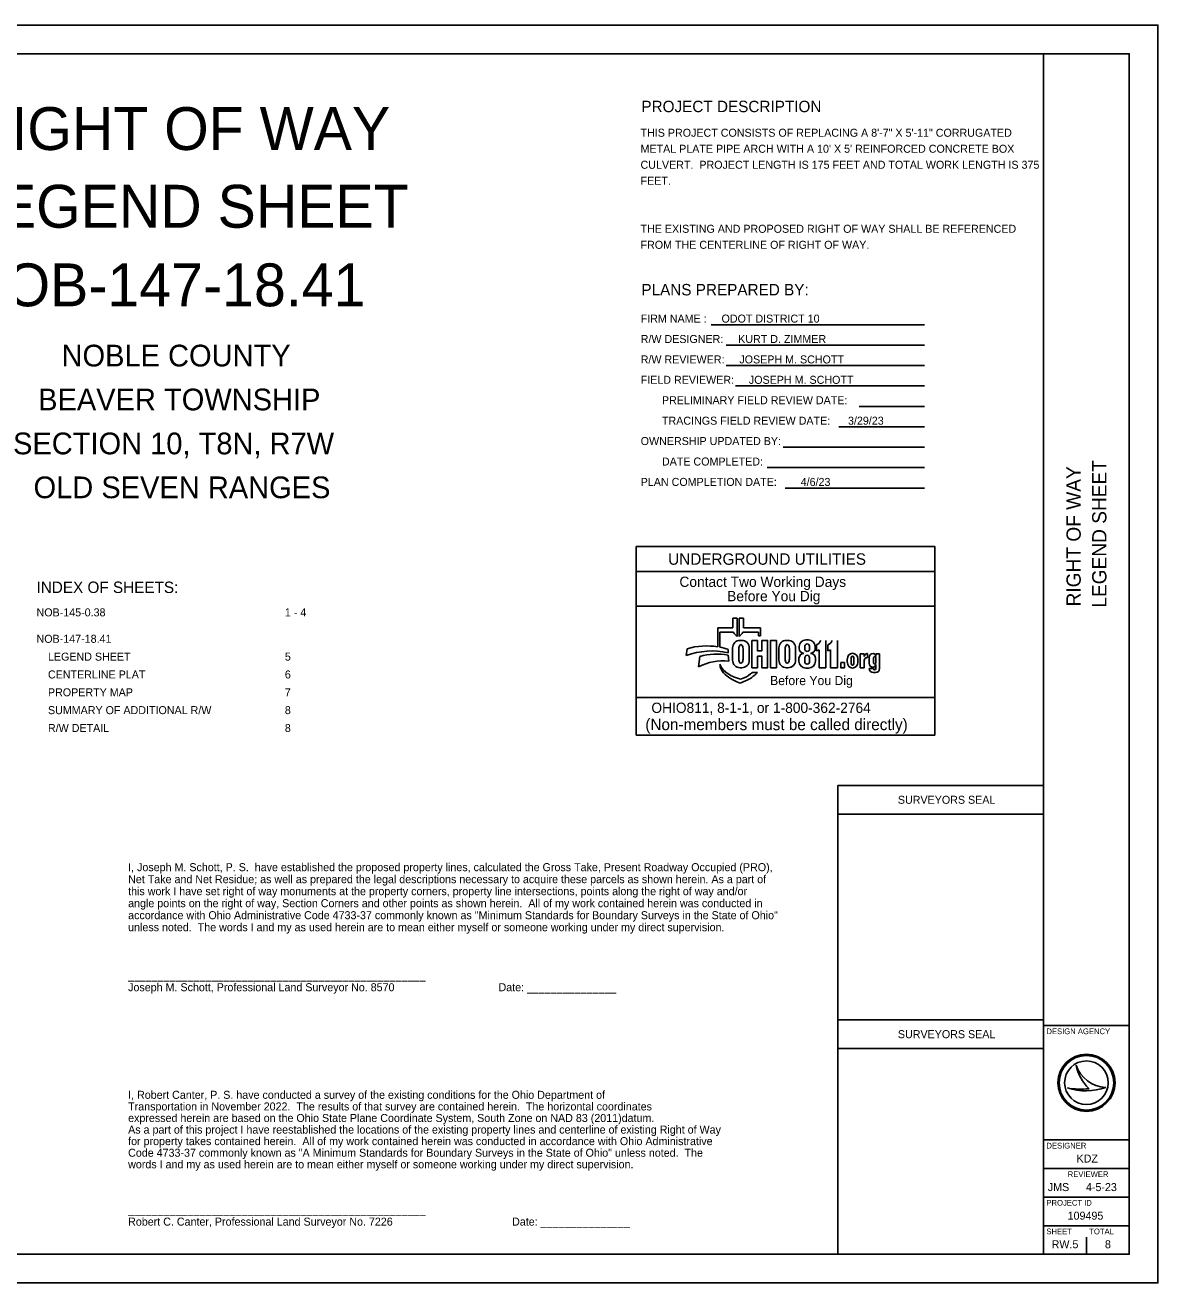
# Model space of a CAD drawing. Extents: x 0 to 34, y 0 to 22.
# Drawn here: x 14.18 to 34, y 0 to 22 of the extents above; entities that cross this region are included whole.
import ezdxf

# ---------------------------------------------------------------- set-up
doc = ezdxf.new("R2010")
doc.units = 0
for name, color, linetype in [('SH_Border', 7, 'Continuous'), ('SH_Cut_Line', 7, 'Continuous'), ('SH_Data', 7, 'Continuous'), ('SH_Text', 7, 'Continuous')]:
    doc.layers.add(name, color=color, linetype=linetype)

msp = doc.modelspace()

# ---------------------------------------------------------------- linework, layer by layer
at = {"layer": 'SH_Border'}
for p, q in [((32, 0.5), (32, 21.5)), ((32, 4.5), (33.5, 4.5)), ((32, 2.5), (33.5, 2.5)), ((32, 2), (33.5, 2)), ((32, 1.5), (33.5, 1.5)), ((32, 1), (33.5, 1))]:
    msp.add_line(p, q, dxfattribs=at)
msp.add_lwpolyline([(1.5, 21.5), (33.5, 21.5), (33.5, 0.5), (1.5, 0.5)], close=True, dxfattribs=at)
at = {"layer": 'SH_Cut_Line'}
msp.add_lwpolyline([(0, 0), (34, 0), (34, 22), (0, 22)], close=True, dxfattribs=at)
at = {"layer": 'SH_Data'}
for p, q in [((26.559, 11.46), (26.296, 11.46)), ((26.296, 11.46), (26.296, 11.125)), ((26.639, 11.626), (26.559, 11.626)), ((26.559, 11.626), (26.559, 11.46)), ((26.639, 11.309), (26.639, 11.626)), ((26.75, 11.626), (26.67, 11.626)), ((26.67, 11.626), (26.67, 11.309)), ((26.75, 11.46), (26.75, 11.626)), ((27.048, 11.46), (26.75, 11.46)), ((27.048, 11.319), (27.048, 11.46)), ((26.334, 11.119), (26.334, 11.383)), ((26.334, 11.383), (26.574, 11.383)), ((26.716, 11.238), (26.691, 11.238)), ((26.735, 11.383), (27.013, 11.383)), ((26.993, 11.237), (26.892, 11.237)), ((26.892, 11.237), (26.892, 10.759)), ((27.013, 11.383), (27.013, 11.319)), ((27.013, 11.319), (27.048, 11.319)), ((27.526, 11.238), (27.502, 11.238)), ((27.887, 11.245), (27.839, 11.245)), ((28.191, 11.237), (28.191, 10.759)), ((28.391, 11.237), (28.391, 10.759)), ((25.761, 11.091), (25.747, 10.974)), ((26.48, 11.023), (26.48, 11.081)), ((26.557, 11.105), (26.557, 10.893)), ((26.666, 10.91), (26.666, 11.092)), ((26.741, 11.092), (26.741, 10.91)), ((26.849, 10.893), (26.849, 11.105)), ((27.368, 11.105), (27.368, 10.893)), ((27.477, 10.91), (27.477, 11.092)), ((27.551, 11.092), (27.551, 10.91)), ((27.66, 10.893), (27.66, 11.105)), ((27.725, 11.131), (27.725, 11.095)), ((27.823, 11.078), (27.823, 11.136)), ((27.904, 11.136), (27.904, 11.078)), ((28.001, 11.095), (28.001, 11.131)), ((28.024, 11.057), (28.024, 11.158)), ((28.073, 10.759), (28.073, 11.071)), ((28.225, 11.057), (28.225, 11.158)), ((28.273, 10.759), (28.273, 11.071)), ((28.86, 11.002), (28.787, 11.002)), ((28.787, 11.002), (28.787, 10.759)), ((28.86, 10.955), (28.86, 11.002)), ((28.921, 11.01), (28.915, 11.01)), ((28.921, 10.936), (28.921, 11.01)), ((29.064, 10.957), (29.064, 11.004)), ((29.064, 11.004), (29.129, 11.004)), ((29.129, 11.004), (29.129, 10.745)), ((25.981, 10.956), (25.959, 10.776)), ((26.333, 10.819), (26.337, 10.792)), ((26.49, 10.873), (26.481, 10.979)), ((26.993, 10.759), (26.993, 10.961)), ((27.719, 10.925), (27.719, 10.874)), ((27.82, 10.865), (27.82, 10.926)), ((27.905, 10.926), (27.905, 10.865)), ((28.007, 10.874), (28.007, 10.925)), ((28.565, 10.85), (28.565, 10.918)), ((28.632, 10.849), (28.632, 10.918)), ((28.68, 10.918), (28.68, 10.849)), ((28.748, 10.918), (28.748, 10.85)), ((28.86, 10.759), (28.86, 10.886)), ((28.909, 10.936), (28.921, 10.936)), ((28.949, 10.837), (28.949, 10.941)), ((29.021, 10.851), (29.021, 10.927)), ((29.064, 10.927), (29.064, 10.851)), ((29.064, 10.745), (29.064, 10.815)), ((26.698, 10.558), (26.609, 10.589)), ((26.691, 10.759), (26.716, 10.759)), ((26.759, 10.585), (26.698, 10.558)), ((26.892, 10.759), (26.993, 10.759)), ((26.991, 10.679), (26.905, 10.679)), ((26.989, 10.676), (26.991, 10.679)), ((27.502, 10.759), (27.526, 10.759)), ((27.84, 10.753), (27.887, 10.753)), ((28.191, 10.759), (28.073, 10.759)), ((28.391, 10.759), (28.273, 10.759)), ((28.787, 10.759), (28.86, 10.759)), ((28.949, 10.745), (29.021, 10.745)), ((29.059, 10.676), (29.019, 10.676)), ((26.633, 10.512), (26.689, 10.488)), ((26.689, 10.488), (26.783, 10.529)), ((30.095, 9.581), (24.87, 9.581)), ((28.4, 8.2), (32, 8.2)), ((28.4, 4.1), (32, 4.1)), ((32.567, 3.81), (32.567, 3.81)), ((32.417, 3.41), (32.417, 3.41)), ((32.75, 3.5), (32.75, 3.5)), ((33.087, 3.419), (33.087, 3.419)), ((32.375, 0.675), (32.375, 0.675)), ((32.75, 0.5), (32.75, 0.8))]:
    msp.add_line(p, q, dxfattribs=at)
for points in [[(24.87, 12.881), (30.095, 12.881), (30.095, 12.441), (24.87, 12.441)], [(24.87, 12.441), (30.095, 12.441), (30.095, 11.836), (24.87, 11.836)], [(24.87, 11.836), (30.095, 11.836), (30.095, 10.241), (24.87, 10.241)], [(28.449, 10.849), (28.515, 10.849), (28.515, 10.759), (28.449, 10.759)], [(24.87, 10.241), (30.095, 10.241), (30.095, 9.581), (24.87, 9.581)], [(28.4, 8.7), (32, 8.7), (32, 4.6), (28.4, 4.6)], [(28.4, 4.6), (32, 4.6), (32, 0.5), (28.4, 0.5)]]:
    msp.add_lwpolyline(points, close=True, dxfattribs=at)
for points in [[(26.993, 10.961), (27.07, 10.961), (27.07, 10.759), (27.171, 10.759), (27.171, 11.237), (27.07, 11.237), (27.07, 11.057), (26.993, 11.057), (26.993, 11.237)], [(27.222, 10.759), (27.325, 10.759), (27.325, 11.237), (27.222, 11.237), (27.222, 10.759)], [(27.805, 11.011), (27.805, 11.011)], [(27.921, 11.011), (27.921, 11.011)]]:
    msp.add_lwpolyline(points, dxfattribs=at)
for radius in [0.5, 0.477, 0.477, 0.382]:
    msp.add_circle((32.75, 3.5), radius, dxfattribs=at)
for centre, radius, start, end in [((26.691, 11.105), 0.134, 90, 180), ((26.711, 11.438), 0.147, 201.9296, 240.7469), ((26.598, 11.438), 0.147, 299.2531, 338.0704), ((26.716, 11.105), 0.134, 0, 90), ((27.502, 11.105), 0.134, 90, 180), ((27.526, 11.105), 0.134, 0, 90), ((27.839, 11.131), 0.114, 90, 180), ((27.887, 11.131), 0.114, 0, 90), ((27.974, 11.281), 0.132, 292.5572, 340.7355), ((28.174, 11.281), 0.132, 292.5572, 340.7355), ((26.199, 9.721), 1.332, 77.8238, 109.8274), ((26.105, 9.917), 1.224, 81.0007, 106.3144), ((26.105, 9.917), 1.224, 72.1402, 79.2074), ((27.805, 10.925), 0.0865, 90, 180), ((27.808, 11.095), 0.0837, 180, 268.1442), ((27.918, 11.095), 0.0837, 272.2058, 0), ((27.921, 10.925), 0.0865, 0, 90), ((28.013, 11.188), 0.132, 275.1733, 297.0931), ((28.213, 11.188), 0.132, 275.1733, 297.0931), ((28.661, 10.918), 0.0956, 92.5886, 180), ((28.652, 10.918), 0.0956, 0, 87.4114), ((28.915, 10.955), 0.0548, 90, 180), ((29.018, 10.941), 0.0686, 92.6865, 180), ((29.012, 10.957), 0.0524, 0, 86.9262), ((26.388, 9.929), 0.95, 83.8248, 116.8021), ((26.28, 9.904), 1.094, 79.44, 105.8467), ((26.613, 10.927), 0.3, 201.0457, 232.5314), ((26.548, 10.828), 0.214, 189.6817, 216.0884), ((26.691, 10.893), 0.134, 180, 270), ((26.716, 10.893), 0.134, 270, 0), ((27.502, 10.893), 0.134, 180, 270), ((27.526, 10.893), 0.134, 270, 0), ((27.84, 10.874), 0.121, 180, 270), ((27.887, 10.874), 0.121, 270, 0), ((28.661, 10.85), 0.0956, 180, 267.4114), ((28.652, 10.85), 0.0956, 272.5886, 0), ((28.909, 10.886), 0.0493, 90, 180), ((29.018, 10.837), 0.0692, 180, 265.7132), ((29.017, 10.815), 0.0467, 264.7825, 0), ((26.748, 10.974), 0.461, 216.0884, 235.7167), ((26.9, 11.302), 0.773, 232.5314, 241.794), ((26.997, 11.339), 0.903, 235.7167, 246.2325), ((26.773, 11.065), 0.504, 241.794, 250.9821), ((26.545, 11.078), 0.538, 293.4582, 312.0712), ((26.545, 11.078), 0.599, 293.4582, 317.8286), ((29.019, 10.745), 0.0699, 180, 270), ((29.059, 10.745), 0.0699, 270, 0), ((33.116, 3.998), 0.58, 198.9257, 198.9319), ((33.347, 3.97), 0.796, 191.6379, 191.6421), ((33.116, 3.998), 0.58, 198.9319, 267.1657), ((33.347, 3.97), 0.796, 191.6421, 226.0947), ((32.739, 4.37), 1.013, 251.4576, 290.0832), ((32.648, 4.654), 1.266, 259.4964, 259.4995), ((32.739, 4.37), 1.013, 251.4527, 251.4576), ((32.648, 4.654), 1.266, 259.4995, 276.6672)]:
    msp.add_arc(centre, radius, start, end, dxfattribs=at)
for centre, major_axis, ratio, start_param, end_param in [((26.703, 11.092), (0, 0.0723), 0.514403, 4.712389, 7.853982), ((27.514, 11.092), (0, 0.0723), 0.514403, 4.712389, 7.853982), ((27.864, 11.136), (0.0404, 0), 0.969373, 0, 3.141593), ((27.864, 11.078), (0.0404, 0), 0.818453, 3.141593, 6.283185), ((26.703, 10.91), (0, 0.0723), 0.514403, 1.570796, 4.712389), ((27.514, 10.91), (0, 0.0723), 0.514403, 1.570796, 4.712389), ((27.862, 10.926), (0, 0.0535), 0.794529, 4.712389, 7.853982), ((27.862, 10.865), (0.0425, 0), 0.959837, 3.141593, 6.283185), ((28.656, 10.918), (0, 0.0434), 0.553236, 4.712389, 7.853982), ((28.656, 10.849), (0, 0.046), 0.522014, 1.570796, 4.712389), ((29.043, 10.927), (0, 0.0275), 0.777179, 4.712389, 7.853982), ((29.043, 10.851), (0, 0.0275), 0.777179, 1.570796, 4.712389), ((29.043, 10.745), (0.0214, 0), 0.959012, 3.141593, 6.283185)]:
    msp.add_ellipse(centre, major_axis=major_axis, ratio=ratio, start_param=start_param, end_param=end_param, dxfattribs=at)
at = {"layer": 'SH_Text'}
for p, q in [((26.181, 16.76), (29.918, 16.76)), ((26.445, 16.403), (29.918, 16.403)), ((26.445, 16.046), (29.918, 16.046)), ((26.609, 15.689), (29.918, 15.689)), ((28.773, 15.331), (29.918, 15.331)), ((28.415, 14.974), (29.918, 14.974)), ((27.445, 14.617), (29.918, 14.617)), ((27.16, 14.26), (29.918, 14.26)), ((27.475, 13.903), (29.918, 13.903))]:
    msp.add_line(p, q, dxfattribs=at)

# ---------------------------------------------------------------- texts
at = {"layer": 'SH_Data'}
for s, height, p in [('RIGHT OF WAY', 0.75, (13.21, 19.816)), ('LEGEND SHEET', 0.75, (13.141, 18.457)), ('NOB-147-18.41', 0.75, (13.108, 17.082)), ('NOBLE COUNTY', 0.38, (14.813, 16.03)), ('BEAVER TOWNSHIP', 0.38, (14.403, 15.262)), ('SECTION 10, T8N, R7W', 0.38, (13.964, 14.493)), ('OLD SEVEN RANGES', 0.38, (14.323, 13.725)), ('UNDERGROUND UTILITIES', 0.2, (25.43, 12.561)), ('Contact Two Working Days', 0.18, (25.627, 12.173)), ('INDEX OF SHEETS:', 0.2, (14.375, 12.067)), ('Before You Dig', 0.18, (26.462, 11.923)), ('NOB-145-0.38', 0.14, (14.375, 11.658)), ('1 - 4', 0.14, (18.721, 11.658)), ('NOB-147-18.41', 0.14, (14.375, 11.196)), ('LEGEND SHEET', 0.14, (14.575, 10.884)), ('5', 0.14, (18.721, 10.884)), ('CENTERLINE PLAT', 0.14, (14.575, 10.572)), ('6', 0.14, (18.721, 10.572)), ('Before You Dig', 0.15972, (27.213, 10.456)), ('PROPERTY MAP', 0.14, (14.575, 10.26)), ('7', 0.14, (18.721, 10.26)), ('OHIO811, 8-1-1, or 1-800-362-2764', 0.18, (25.136, 9.969)), ('SUMMARY OF ADDITIONAL R/W', 0.14, (14.575, 9.948)), ('8', 0.14, (18.721, 9.948)), ('R/W DETAIL', 0.14, (14.575, 9.636)), ('8', 0.14, (18.721, 9.636)), ('(Non-members must be called directly)', 0.2, (25.03, 9.668)), ('SURVEYORS SEAL', 0.14, (29.45, 8.38)), ('SURVEYORS SEAL', 0.14, (29.45, 4.28)), ('DESIGN AGENCY', 0.1, (32.05, 4.35)), ('DESIGNER', 0.1, (32.05, 2.35)), ('KDZ', 0.14, (32.577, 2.105)), ('REVIEWER', 0.1, (32.422, 1.85)), ('JMS', 0.14, (32.074, 1.605)), ('4-5-23', 0.14, (32.741, 1.605)), ('PROJECT ID', 0.1, (32.05, 1.35)), ('109495', 0.14, (32.421, 1.105)), ('SHEET', 0.1, (32.05, 0.85)), ('TOTAL', 0.1, (32.8, 0.85)), ('RW.5', 0.14, (32.141, 0.605)), ('8', 0.14, (33.074, 0.605))]:
    msp.add_text(s, height=height, dxfattribs=at).set_placement(p)
for s, p in [('LEGEND SHEET', (33.1, 11.81)), ('RIGHT OF WAY', (32.65, 11.832))]:
    msp.add_text(s, height=0.25, rotation=90, dxfattribs=at).set_placement(p)
at = {"layer": 'SH_Text'}
for s, height, p in [('PROJECT DESCRIPTION', 0.2, (24.961, 20.478)), ('THIS PROJECT CONSISTS OF REPLACING A 8\'-7" X 5\'-11" CORRUGATED ', 0.14, (24.946, 20.048)), ("METAL PLATE PIPE ARCH WITH A 10' X 5' REINFORCED CONCRETE BOX ", 0.14, (24.946, 19.768)), ('CULVERT.  PROJECT LENGTH IS 175 FEET AND TOTAL WORK LENGTH IS 375 ', 0.14, (24.946, 19.488)), ('FEET.', 0.14, (24.946, 19.208)), ('THE EXISTING AND PROPOSED RIGHT OF WAY SHALL BE REFERENCED ', 0.14, (24.946, 18.368)), ('FROM THE CENTERLINE OF RIGHT OF WAY.', 0.14, (24.946, 18.088)), ('PLANS PREPARED BY:', 0.2, (24.961, 17.273)), ('FIRM NAME :     ODOT DISTRICT 10', 0.14, (24.949, 16.797)), ('R/W DESIGNER:     KURT D. ZIMMER', 0.14, (24.949, 16.44)), ('R/W REVIEWER:     JOSEPH M. SCHOTT', 0.14, (24.949, 16.083)), ('FIELD REVIEWER:     JOSEPH M. SCHOTT', 0.14, (24.949, 15.726)), ('PRELIMINARY FIELD REVIEW DATE:', 0.14, (25.321, 15.369)), ('TRACINGS FIELD REVIEW DATE:      3/29/23        ', 0.14, (25.321, 15.011)), ('OWNERSHIP UPDATED BY:', 0.14, (24.949, 14.655)), ('DATE COMPLETED:', 0.14, (25.321, 14.297)), ('PLAN COMPLETION DATE:', 0.14, (24.949, 13.94)), ('4/6/23', 0.14, (27.749, 13.94)), ('I, Joseph M. Schott, P. S.  have established the proposed property lines, calculated the Gross Take, Present Roadway Occupied (PRO),', 0.14, (15.978, 7.201)), ('Net Take and Net Residue; as well as prepared the legal descriptions necessary to acquire these parcels as shown herein. As a part of', 0.14, (15.978, 6.991)), ('this work I have set right of way monuments at the property corners, property line intersections, points along the right of way and/or', 0.14, (15.978, 6.781)), ('angle points on the right of way, Section Corners and other points as shown herein.  All of my work contained herein was conducted in', 0.14, (15.978, 6.571)), ('accordance with Ohio Administrative Code 4733-37 commonly known as "Minimum Standards for Boundary Surveys in the State of Ohio"', 0.14, (15.978, 6.361)), ('unless noted.  The words I and my as used herein are to mean either myself or someone working under my direct supervision.', 0.14, (15.978, 6.151)), ('__________________________________________________', 0.14, (15.978, 5.311)), ('Joseph M. Schott, Professional Land Surveyor No. 8570                                   Date: _______________                  ', 0.14, (15.978, 5.101)), ('I, Robert Canter, P. S. have conducted a survey of the existing conditions for the Ohio Department of', 0.14, (15.978, 3.219)), ('Transportation in November 2022.  The results of that survey are contained herein.  The horizontal coordinates', 0.14, (15.978, 3.016)), ('expressed herein are based on the Ohio State Plane Coordinate System, South Zone on NAD 83 (2011)datum.', 0.14, (15.978, 2.814)), ('As a part of this project I have reestablished the locations of the existing property lines and centerline of existing Right of Way ', 0.14, (15.978, 2.611)), ('for property takes contained herein.  All of my work contained herein was conducted in accordance with Ohio Administrative ', 0.14, (15.978, 2.409)), ('Code 4733-37 commonly known as "A Minimum Standards for Boundary Surveys in the State of Ohio" unless noted.  The ', 0.14, (15.978, 2.206)), ('words I and my as used herein are to mean either myself or someone working under my direct supervision.', 0.14, (15.978, 2.004)), ('__________________________________________________', 0.14, (15.978, 1.211)), ('Robert C. Canter, Professional Land Surveyor No. 7226                           ', 0.14, (15.978, 1.001)), ('Date: _______________ ', 0.14, (22.698, 1.001))]:
    msp.add_text(s, height=height, dxfattribs=at).set_placement(p)

doc.saveas('drawing.dxf')
